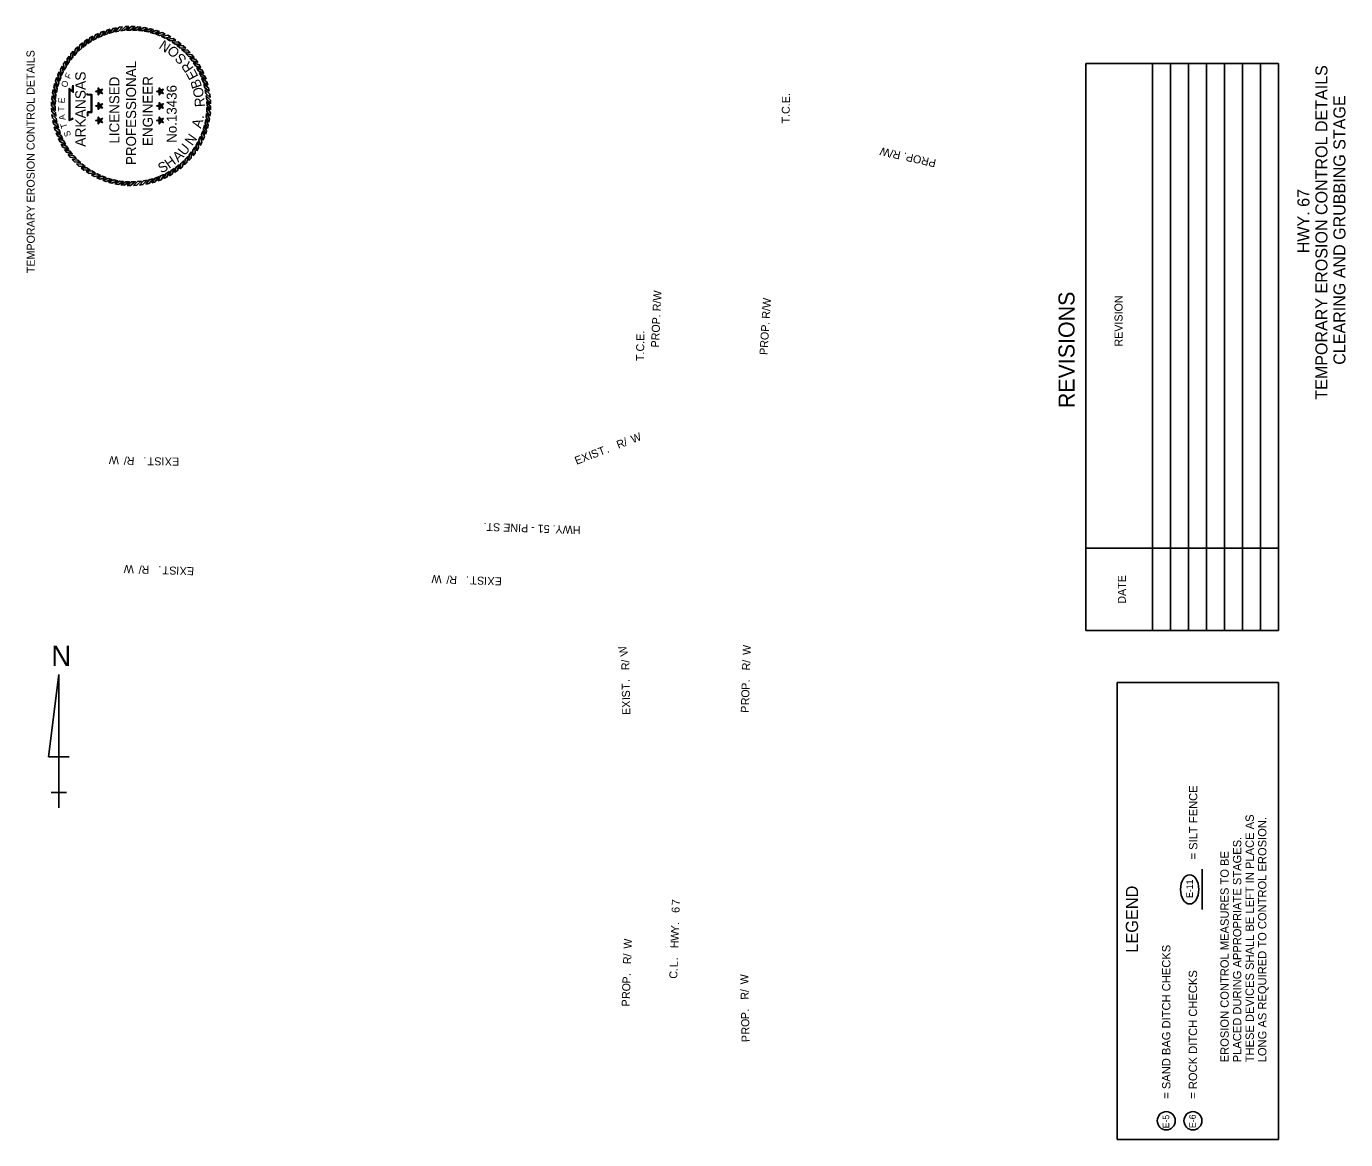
# Model space of a CAD drawing. Extents: x 992013 to 993002, y 1842718 to 1844294.
# Drawn here: x 992013 to 993002, y 1843459 to 1844294 of the extents above; entities that cross this region are included whole.
import ezdxf

# ---------------------------------------------------------------- set-up
doc = ezdxf.new("R2010")
doc.units = 0
for name, color, linetype in [('60', 7, 'Continuous'), ('63', 7, 'Continuous'), ('G-ANNO-SYMB', 7, 'Continuous'), ('G-ANNO-TEXT', 7, 'Continuous'), ('G-Border-Sheet', 7, 'Continuous'), ('Level 1', 7, 'Continuous'), ('Level 44', 7, 'Continuous'), ('R_Draft', 7, 'Continuous')]:
    doc.layers.add(name, color=color, linetype=linetype)

msp = doc.modelspace()

# ---------------------------------------------------------------- linework, layer by layer
at = {"layer": '63'}
for p, q in [((992036.87, 1843807.9), (992029.18, 1843746.36)), ((992036.87, 1843707.9), (992036.87, 1843807.9)), ((992036.87, 1843807.9), (992036.87, 1843730.97)), ((992029.18, 1843746.36), (992044.56, 1843746.36)), ((992036.87, 1843707.9), (992036.87, 1843730.97)), ((992036.87, 1843719.43), (992031.1, 1843719.43)), ((992031.1, 1843719.43), (992042.64, 1843719.43)), ((992036.87, 1843707.9), (992036.87, 1843719.43))]:
    msp.add_line(p, q, dxfattribs=at)
at = {"layer": 'G-ANNO-SYMB'}
for points in [[(992084.69, 1844293.56), (992082.14, 1844293.23), (992079.02, 1844289.88), (992081.75, 1844290.4)], [(992089.36, 1844293.87), (992086.8, 1844293.75), (992083.43, 1844290.66), (992086.18, 1844290.96)], [(992094.04, 1844293.82), (992091.48, 1844293.9), (992087.88, 1844291.08), (992090.65, 1844291.17)], [(992098.71, 1844293.41), (992096.16, 1844293.68), (992092.35, 1844291.16), (992095.12, 1844291.03)], [(992103.33, 1844292.63), (992100.81, 1844293.1), (992096.81, 1844290.88), (992099.56, 1844290.53)], [(992058.45, 1844284.2), (992056.34, 1844282.75), (992055.07, 1844278.35), (992057.26, 1844280.05)], [(992062.47, 1844286.6), (992060.25, 1844285.32), (992058.65, 1844281.04), (992060.96, 1844282.56)], [(992066.67, 1844288.68), (992064.35, 1844287.58), (992062.42, 1844283.44), (992064.85, 1844284.78)], [(992071.02, 1844290.43), (992068.62, 1844289.52), (992066.37, 1844285.54), (992068.89, 1844286.68)], [(992075.49, 1844291.83), (992073.02, 1844291.11), (992070.47, 1844287.32), (992073.08, 1844288.25)], [(992080.05, 1844292.87), (992077.54, 1844292.35), (992074.7, 1844288.77), (992077.37, 1844289.5)], [(992107.87, 1844291.48), (992105.4, 1844292.15), (992101.23, 1844290.26), (992103.95, 1844289.7)], [(992112.31, 1844289.99), (992109.9, 1844290.85), (992105.6, 1844289.29), (992108.26, 1844288.51)], [(992116.62, 1844288.15), (992114.28, 1844289.2), (992109.87, 1844287.98), (992112.47, 1844287)], [(992120.77, 1844285.98), (992118.52, 1844287.21), (992114.03, 1844286.33), (992116.54, 1844285.16)], [(992124.74, 1844283.49), (992122.59, 1844284.89), (992118.05, 1844284.37), (992120.46, 1844283)], [(992047.69, 1844275.2), (992045.97, 1844273.3), (992045.77, 1844268.73), (992047.5, 1844270.9)], [(992051.04, 1844278.48), (992049.17, 1844276.72), (992048.62, 1844272.18), (992050.51, 1844274.2)], [(992054.63, 1844281.48), (992052.64, 1844279.87), (992051.72, 1844275.39), (992053.77, 1844277.26)], [(992128.5, 1844280.69), (992126.47, 1844282.26), (992121.9, 1844282.1), (992124.19, 1844280.54)], [(992132.03, 1844277.61), (992130.13, 1844279.33), (992125.56, 1844279.53), (992127.72, 1844277.8)], [(992135.31, 1844274.27), (992133.54, 1844276.13), (992129, 1844276.69), (992131.03, 1844274.79)], [(992138.31, 1844270.67), (992136.7, 1844272.67), (992132.22, 1844273.58), (992134.08, 1844271.53)], [(992039.33, 1844263.95), (992038.1, 1844261.69), (992038.97, 1844257.2), (992040.15, 1844259.71)], [(992041.82, 1844267.91), (992040.42, 1844265.76), (992040.93, 1844261.22), (992042.31, 1844263.63)], [(992044.61, 1844271.67), (992043.05, 1844269.64), (992043.2, 1844265.07), (992044.76, 1844267.36)], [(992141.02, 1844266.85), (992139.57, 1844268.97), (992135.18, 1844270.23), (992136.88, 1844268.04)], [(992143.43, 1844262.83), (992142.15, 1844265.06), (992137.87, 1844266.66), (992139.39, 1844264.34)], [(992035.32, 1844255.49), (992034.46, 1844253.07), (992036.02, 1844248.77), (992036.79, 1844251.43)], [(992037.16, 1844259.79), (992036.11, 1844257.45), (992037.33, 1844253.05), (992038.31, 1844255.64)], [(992145.51, 1844258.64), (992144.41, 1844260.95), (992140.27, 1844262.89), (992141.6, 1844260.46)], [(992147.26, 1844254.29), (992146.34, 1844256.69), (992142.36, 1844258.94), (992143.5, 1844256.41)], [(992148.66, 1844249.82), (992147.93, 1844252.28), (992144.14, 1844254.84), (992145.08, 1844252.23)], [(992032.68, 1844246.5), (992032.21, 1844243.98), (992034.42, 1844239.98), (992034.77, 1844242.73)], [(992033.82, 1844251.05), (992033.15, 1844248.57), (992035.05, 1844244.41), (992035.61, 1844247.12)], [(992067.31, 1844245.15), (992066.47, 1844245.76), (992064.58, 1844245.15), (992066.47, 1844244.54)], [(992067.31, 1844245.15), (992067.63, 1844246.14), (992066.47, 1844247.74), (992066.47, 1844245.76)], [(992067.31, 1844245.15), (992066.47, 1844244.54), (992066.47, 1844242.56), (992067.63, 1844244.16)], [(992067.31, 1844245.15), (992068.35, 1844245.15), (992069.52, 1844246.75), (992067.63, 1844246.14)], [(992067.31, 1844245.15), (992067.63, 1844244.16), (992069.52, 1844243.55), (992068.35, 1844245.15)], [(992112.99, 1844245.15), (992112.15, 1844245.76), (992110.26, 1844245.15), (992112.15, 1844244.54)], [(992112.99, 1844245.15), (992113.31, 1844246.14), (992112.15, 1844247.74), (992112.15, 1844245.76)], [(992112.99, 1844245.15), (992112.15, 1844244.54), (992112.15, 1844242.56), (992113.31, 1844244.16)], [(992112.99, 1844245.15), (992114.03, 1844245.15), (992115.2, 1844246.75), (992113.31, 1844246.14)], [(992112.99, 1844245.15), (992113.31, 1844244.16), (992115.2, 1844243.55), (992114.03, 1844245.15)], [(992149.7, 1844245.25), (992149.17, 1844247.76), (992145.59, 1844250.61), (992146.33, 1844247.94)], [(992150.38, 1844240.62), (992150.05, 1844243.16), (992146.71, 1844246.28), (992147.23, 1844243.56)], [(992031.48, 1844237.22), (992031.41, 1844234.65), (992034.22, 1844231.05), (992034.14, 1844233.82)], [(992031.9, 1844241.88), (992031.62, 1844239.33), (992034.15, 1844235.52), (992034.28, 1844238.29)], [(992067.31, 1844234.24), (992066.47, 1844234.85), (992064.58, 1844234.24), (992066.47, 1844233.63)], [(992067.31, 1844234.24), (992067.63, 1844235.23), (992066.47, 1844236.83), (992066.47, 1844234.85)], [(992067.31, 1844234.24), (992066.47, 1844233.63), (992066.47, 1844231.65), (992067.63, 1844233.25)], [(992067.31, 1844234.24), (992068.35, 1844234.24), (992069.52, 1844235.84), (992067.63, 1844235.23)], [(992067.31, 1844234.24), (992067.63, 1844233.25), (992069.52, 1844232.64), (992068.35, 1844234.24)], [(992112.99, 1844234.24), (992112.15, 1844234.85), (992110.26, 1844234.24), (992112.15, 1844233.63)], [(992112.99, 1844234.24), (992113.31, 1844235.23), (992112.15, 1844236.83), (992112.15, 1844234.85)], [(992112.99, 1844234.24), (992112.15, 1844233.63), (992112.15, 1844231.65), (992113.31, 1844233.25)], [(992112.99, 1844234.24), (992114.03, 1844234.24), (992115.2, 1844235.84), (992113.31, 1844235.23)], [(992112.99, 1844234.24), (992113.31, 1844233.25), (992115.2, 1844232.64), (992114.03, 1844234.24)], [(992150.7, 1844235.94), (992150.57, 1844238.51), (992147.48, 1844241.88), (992147.79, 1844239.12)], [(992150.65, 1844231.26), (992150.72, 1844233.83), (992147.91, 1844237.43), (992148, 1844234.66)], [(992031.43, 1844232.53), (992031.56, 1844229.97), (992034.65, 1844226.6), (992034.34, 1844229.36)], [(992031.75, 1844227.86), (992032.08, 1844225.32), (992035.42, 1844222.2), (992034.9, 1844224.92)], [(992067.31, 1844223.33), (992066.47, 1844223.94), (992064.58, 1844223.33), (992066.47, 1844222.72)], [(992067.31, 1844223.33), (992067.63, 1844224.32), (992066.47, 1844225.92), (992066.47, 1844223.94)], [(992067.31, 1844223.33), (992068.35, 1844223.33), (992069.52, 1844224.93), (992067.63, 1844224.32)], [(992112.99, 1844223.33), (992112.15, 1844223.94), (992110.26, 1844223.33), (992112.15, 1844222.72)], [(992112.99, 1844223.33), (992113.31, 1844224.32), (992112.15, 1844225.92), (992112.15, 1844223.94)], [(992112.99, 1844223.33), (992114.03, 1844223.33), (992115.2, 1844224.93), (992113.31, 1844224.32)], [(992148.31, 1844217.43), (992148.98, 1844219.91), (992147.08, 1844224.07), (992146.52, 1844221.36)], [(992149.45, 1844221.98), (992149.92, 1844224.5), (992147.71, 1844228.5), (992147.36, 1844225.75)], [(992150.23, 1844226.59), (992150.51, 1844229.15), (992147.98, 1844232.96), (992147.85, 1844230.19)], [(992032.43, 1844223.23), (992032.96, 1844220.72), (992036.54, 1844217.87), (992035.81, 1844220.54)], [(992033.48, 1844218.66), (992034.2, 1844216.2), (992037.99, 1844213.64), (992037.05, 1844216.25)], [(992034.88, 1844214.19), (992035.79, 1844211.79), (992039.77, 1844209.54), (992038.63, 1844212.07)], [(992067.31, 1844223.33), (992066.47, 1844222.72), (992066.47, 1844220.74), (992067.63, 1844222.34)], [(992067.31, 1844223.33), (992067.63, 1844222.34), (992069.52, 1844221.73), (992068.35, 1844223.33)], [(992112.99, 1844223.33), (992112.15, 1844222.72), (992112.15, 1844220.74), (992113.31, 1844222.34)], [(992112.99, 1844223.33), (992113.31, 1844222.34), (992115.2, 1844221.73), (992114.03, 1844223.33)], [(992144.98, 1844208.69), (992146.02, 1844211.03), (992144.8, 1844215.43), (992143.82, 1844212.84)], [(992146.81, 1844212.99), (992147.68, 1844215.41), (992146.11, 1844219.71), (992145.34, 1844217.05)], [(992036.62, 1844209.84), (992037.72, 1844207.53), (992041.87, 1844205.59), (992040.53, 1844208.02)], [(992038.7, 1844205.65), (992039.98, 1844203.42), (992044.27, 1844201.82), (992042.74, 1844204.14)], [(992140.31, 1844200.57), (992141.72, 1844202.72), (992141.2, 1844207.26), (992139.83, 1844204.85)], [(992142.8, 1844204.53), (992144.03, 1844206.79), (992143.16, 1844211.27), (992141.98, 1844208.77)], [(992041.11, 1844201.63), (992042.56, 1844199.51), (992046.95, 1844198.25), (992045.25, 1844200.44)], [(992043.82, 1844197.81), (992045.43, 1844195.81), (992049.91, 1844194.9), (992048.05, 1844196.95)], [(992046.83, 1844194.21), (992048.59, 1844192.35), (992053.13, 1844191.79), (992051.11, 1844193.69)], [(992131.09, 1844190), (992132.96, 1844191.76), (992133.51, 1844196.3), (992131.62, 1844194.28)], [(992134.44, 1844193.28), (992136.16, 1844195.18), (992136.36, 1844199.75), (992134.63, 1844197.58)], [(992137.52, 1844196.81), (992139.09, 1844198.84), (992138.93, 1844203.41), (992137.37, 1844201.12)], [(992050.1, 1844190.87), (992052.01, 1844189.14), (992056.57, 1844188.95), (992054.41, 1844190.68)], [(992053.63, 1844187.79), (992055.66, 1844186.22), (992060.23, 1844186.38), (992057.94, 1844187.94)], [(992057.39, 1844184.99), (992059.54, 1844183.59), (992064.08, 1844184.11), (992061.68, 1844185.48)], [(992115.46, 1844179.8), (992117.78, 1844180.9), (992119.71, 1844185.04), (992117.28, 1844183.7)], [(992119.66, 1844181.88), (992121.88, 1844183.16), (992123.48, 1844187.44), (992121.17, 1844185.92)], [(992123.68, 1844184.28), (992125.8, 1844185.73), (992127.06, 1844190.13), (992124.87, 1844188.43)], [(992127.5, 1844187), (992129.5, 1844188.61), (992130.41, 1844193.09), (992128.36, 1844191.22)], [(992061.36, 1844182.5), (992063.61, 1844181.27), (992068.1, 1844182.14), (992065.59, 1844183.32)], [(992065.51, 1844180.33), (992067.85, 1844179.28), (992072.26, 1844180.5), (992069.67, 1844181.48)], [(992069.82, 1844178.49), (992072.24, 1844177.63), (992076.53, 1844179.19), (992073.87, 1844179.97)], [(992074.26, 1844177), (992076.74, 1844176.33), (992080.9, 1844178.22), (992078.18, 1844178.78)], [(992078.8, 1844175.85), (992081.32, 1844175.38), (992085.32, 1844177.6), (992082.57, 1844177.94)], [(992083.42, 1844175.07), (992085.97, 1844174.8), (992089.78, 1844177.32), (992087.02, 1844177.45)], [(992088.09, 1844174.65), (992090.65, 1844174.58), (992094.25, 1844177.4), (992091.48, 1844177.31)], [(992092.77, 1844174.6), (992095.33, 1844174.73), (992098.7, 1844177.82), (992095.95, 1844177.52)], [(992097.44, 1844174.92), (992099.99, 1844175.25), (992103.11, 1844178.6), (992100.38, 1844178.08)], [(992102.08, 1844175.61), (992104.59, 1844176.13), (992107.44, 1844179.71), (992104.76, 1844178.98)], [(992106.65, 1844176.65), (992109.11, 1844177.37), (992111.66, 1844181.16), (992109.06, 1844180.22)], [(992111.12, 1844178.05), (992113.51, 1844178.96), (992115.76, 1844182.94), (992113.24, 1844181.8)]]:
    msp.add_lwpolyline(points, close=True, dxfattribs=at)
for points in [[(992047.77, 1844224.68), (992044.75, 1844223.29), (992044.74, 1844247.36), (992047.27, 1844245.34), (992047.24, 1844246.98), (992047.23, 1844248.34), (992047.38, 1844249.71)], [(992047.61, 1844225.03), (992045.13, 1844223.89), (992045.12, 1844246.56), (992047.66, 1844244.55), (992047.63, 1844246.98), (992047.61, 1844248.33), (992047.75, 1844249.67)], [(992057.55, 1844243.32), (992057.97, 1844242.82), (992058.61, 1844242.64), (992059.91, 1844242.5), (992061.21, 1844242.5), (992061.21, 1844229.83), (992059.35, 1844229.83), (992058.57, 1844229.83), (992058.3, 1844228.96), (992058.3, 1844227.2), (992057.96, 1844226.97)], [(992057.85, 1844243.56), (992058.18, 1844243.15), (992058.68, 1844243.02), (992059.93, 1844242.88), (992061.59, 1844242.88), (992061.59, 1844229.45), (992059.35, 1844229.45), (992058.85, 1844229.45), (992058.68, 1844228.9), (992058.68, 1844226.99), (992058.16, 1844226.65)]]:
    msp.add_lwpolyline(points, dxfattribs=at)
at = {"layer": 'G-Border-Sheet'}
for p, q in [((992951.38, 1843801.93), (992830.33, 1843801.93)), ((992830.33, 1843459.27), (992830.33, 1843801.93)), ((992951.38, 1843459.27), (992951.38, 1843801.93)), ((992951.38, 1843459.27), (992830.33, 1843459.27))]:
    msp.add_line(p, q, dxfattribs=at)
at = {"layer": 'Level 1'}
for centre, major_axis, ratio in [((992884.7, 1843646.9), (0, 10.96), 0.622952), ((992867.16, 1843473.37), (0, -6.88), 0.97521), ((992887.16, 1843473.37), (0, -6.88), 0.97521)]:
    msp.add_ellipse(centre, major_axis=major_axis, ratio=ratio, dxfattribs=at)
at = {"layer": 'Level 44'}
msp.add_lwpolyline([(992894.03, 1843631.84), (992894.02, 1843661.96)], dxfattribs=at)
at = {"layer": 'R_Draft'}
for p, q in [((992806.88, 1843840.99), (992806.88, 1844265.99)), ((992806.88, 1844265.99), (992951.38, 1844265.99)), ((992856.88, 1843840.99), (992856.88, 1844265.99)), ((992870.38, 1843840.99), (992870.38, 1844265.99)), ((992883.88, 1843840.99), (992883.88, 1844265.99)), ((992897.38, 1843840.99), (992897.38, 1844265.99)), ((992897.38, 1843840.99), (992897.38, 1844265.99)), ((992910.88, 1843840.99), (992910.88, 1844265.99)), ((992924.38, 1843840.99), (992924.38, 1844265.99)), ((992937.88, 1843840.99), (992937.88, 1844265.99)), ((992951.38, 1843840.99), (992951.38, 1844265.99)), ((992806.88, 1843902.8), (992951.38, 1843902.8)), ((992806.88, 1843840.99), (992951.38, 1843840.99))]:
    msp.add_line(p, q, dxfattribs=at)

# ---------------------------------------------------------------- texts
at = {"layer": '60'}
for s, p in [('TEMPORARY EROSION CONTROL DETAILS', (992988.01, 1844014.05)), ('CLEARING AND GRUBBING STAGE ', (993001.51, 1844040.2)), ('HWY. 67 ', (992974.51, 1844123.82))]:
    msp.add_text(s, height=9, rotation=90, dxfattribs=at).set_placement(p)
at = {"layer": '63'}
msp.add_text('N', height=15.38, rotation=0, dxfattribs=at).set_placement((992031.24, 1843814.31))
at = {"layer": 'G-ANNO-SYMB'}
for s, height, rotation, p in [('N', 7.5, 146.10067, (992121.5, 1844279.98)), ('O', 7.5, 134.77573, (992128.25, 1844274.77)), ('S', 7.5, 133.48784, (992133.23, 1844269.62)), ('PROFESSIONAL', 7.5, 90, (992094.82, 1844189.95)), ('R', 7.5, 125.65967, (992138.33, 1844262.72)), ('F', 4.75, 65.36282, (992045.3, 1844254.08)), ('ARKANSAS', 7.747, 90, (992056.98, 1844203.62)), ('LICENSED', 7.5, 90, (992082.27, 1844206.03)), ('ENGINEER', 7.5, 90, (992107.36, 1844204.24)), ('E', 7.5, 117.83149, (992141.65, 1844256.38)), ('B', 7.5, 108.88501, (992144.36, 1844248.81)), ('O', 4.75, 71.2218, (992042.8, 1844247.68)), ('No.13436', 7.47, 90, (992125.24, 1844206.61)), ('O', 7.5, 101.42961, (992145.95, 1844241.29)), ('E', 4.75, 86.67203, (992041.17, 1844236.15)), ('R', 7.5, 93.22866, (992146.43, 1844233.62)), ('T', 4.75, 91.47887, (992041.03, 1844230.08)), ('A', 4.75, 98.67877, (992041.97, 1844223.95)), ('.', 7.5, 81.30002, (992145.48, 1844224.42)), ('T', 4.75, 106.90148, (992043.48, 1844218.18)), ('S', 4.75, 109.77256, (992046.19, 1844212.15)), ('A', 7.5, 73.09908, (992143.3, 1844217.05)), ('U', 7.5, 50.90262, (992131.28, 1844196.42)), ('N', 7.5, 54.93262, (992136.86, 1844203.97)), ('H', 7.5, 35.61905, (992119.54, 1844186.98)), ('A', 7.5, 43.44722, (992126.39, 1844191.74)), ('S', 7.5, 28.16364, (992113.66, 1844183.56))]:
    msp.add_text(s, height=height, rotation=rotation, dxfattribs=at).set_placement(p)
at = {"layer": 'G-ANNO-TEXT'}
msp.add_text('TEMPORARY EROSION CONTROL DETAILS', height=6, rotation=90.07909, dxfattribs=at).set_placement((992018.89, 1844108.85))
at = {"layer": 'Level 1'}
for s, height, p in [('= SILT FENCE', 6.25, (992890.48, 1843669.33)), ('THESE DEVICES SHALL BE LEFT IN PLACE AS ', 6.25, (992932.84, 1843517.24)), ('LONG AS REQUIRED TO CONTROL EROSION.', 6.25, (992942.25, 1843517.24)), ('PLACED DURING APPROPRIATE STAGES. ', 6.25, (992923.43, 1843517.24)), ('EROSION CONTROL MEASURES TO BE', 6.25, (992914.02, 1843517.24)), ('E-11 ', 4.876, (992887.1, 1843640.5)), ('= SAND BAG DITCH CHECKS', 6.25, (992870.28, 1843489.9)), ('= ROCK DITCH CHECKS', 6.25, (992890.28, 1843489.9)), ('E-5 ', 4.876, (992869.38, 1843467.73)), ('E-6 ', 4.876, (992889.29, 1843467.95))]:
    msp.add_text(s, height=height, rotation=90.00001, dxfattribs=at).set_placement(p)
at = {"layer": 'Level 44'}
msp.add_text('LEGEND', height=9.143, rotation=90.00001, dxfattribs=at).set_placement((992846.03, 1843599.41))
at = {"layer": 'R_Draft'}
for s, height, rotation, p in [('T.C.E.', 6, 89.40901, (992584.79, 1844221.09)), ('PROP. R/W', 6, 167.44815, (992695, 1844194.05)), ('PROP. R/W', 6, 87.28268, (992486.79, 1844053.02)), ('PROP. R/W', 6, 86.36556, (992568.15, 1844047.4)), ('REVISIONS', 12, 90, (992798.38, 1844007.65)), ('REVISION', 6, 90, (992834.38, 1844053.86)), ('T.C.E.', 6, 89.40901, (992475.66, 1844042.97)), ('W', 6, 20.9463, (992467.19, 1843981.28)), ('S', 6, 20.9463, (992437.32, 1843969.85)), ('T', 6, 20.9463, (992442.61, 1843971.88)), ('R', 6, 20.9463, (992456.42, 1843977.16)), ('/', 6, 20.9463, (992461.71, 1843979.19)), ('W', 6, 178.24464, (992082.11, 1843971.49)), ('/', 6, 178.24464, (992087.97, 1843971.31)), ('R', 6, 178.24464, (992093.64, 1843971.13)), ('.', 6, 178.24464, (992102.56, 1843970.86)), ('T', 6, 179.30223, (992108.31, 1843970.81)), ('S', 6, 179.30223, (992113.98, 1843970.74)), ('I', 6, 179.30223, (992115.96, 1843970.72)), ('X', 6, 179.30223, (992121.72, 1843970.65)), ('E', 6, 179.30223, (992127.11, 1843970.58)), ('E', 6, 20.9463, (992425.05, 1843965.15)), ('X', 6, 20.9463, (992430.08, 1843967.08)), ('I', 6, 20.9463, (992435.46, 1843969.14)), ('.', 6, 20.9463, (992448.08, 1843973.97)), ('HWY. 51 - PINE ST.', 6, 178.05575, (992428.12, 1843919.22)), ('W', 6, 178.15992, (992093.27, 1843889.83)), ('/', 6, 178.15992, (992099.12, 1843889.65)), ('R', 6, 178.15992, (992104.79, 1843889.46)), ('.', 6, 178.15992, (992113.71, 1843889.18)), ('T', 6, 178.15992, (992119.57, 1843888.99)), ('S', 6, 178.15992, (992125.24, 1843888.81)), ('I', 6, 178.15992, (992127.22, 1843888.74)), ('X', 6, 178.15992, (992132.98, 1843888.56)), ('E', 6, 178.15992, (992138.36, 1843888.38)), ('W', 6, 178.05575, (992324, 1843882.29)), ('/', 6, 178.05575, (992329.86, 1843882.1)), ('R', 6, 178.05575, (992335.52, 1843881.9)), ('.', 6, 178.05575, (992344.45, 1843881.6)), ('T', 6, 178.05575, (992350.3, 1843881.4)), ('S', 6, 178.05575, (992355.97, 1843881.21)), ('I', 6, 178.05575, (992357.95, 1843881.14)), ('X', 6, 178.05575, (992363.71, 1843880.95)), ('E', 6, 178.05575, (992369.1, 1843880.76)), ('DATE', 6, 90, (992836.88, 1843861.06)), ('W', 6, 104.91415, (992463.85, 1843822.71)), ('W', 6, 88.2004, (992555.51, 1843822.51)), ('/', 6, 91.02618, (992464.63, 1843816.94)), ('/', 6, 88.2004, (992555.32, 1843816.65)), ('R', 6, 91.02618, (992464.73, 1843811.28)), ('R', 6, 88.2004, (992555.14, 1843810.98)), ('T', 6, 91.02618, (992465, 1843796.49)), ('.', 6, 91.02618, (992464.89, 1843802.35)), ('P', 6, 88.2004, (992554.69, 1843796.39)), ('.', 6, 88.2004, (992554.86, 1843802.06)), ('S', 6, 91.02618, (992465.1, 1843790.82)), ('I', 6, 91.02618, (992465.14, 1843788.84)), ('R', 6, 88.2004, (992554.32, 1843784.87)), ('O', 6, 88.2004, (992554.5, 1843790.54)), ('X', 6, 91.02618, (992465.24, 1843783.08)), ('E', 6, 91.02618, (992465.34, 1843777.69)), ('P', 6, 88.2004, (992554.15, 1843779.2)), ('6', 6, 88.03611, (992502.24, 1843629.19)), ('7', 6, 88.03611, (992502.43, 1843634.86)), ('.', 6, 88.03611, (992501.93, 1843620.27)), ('W', 6, 88.03611, (992501.52, 1843608.09)), ('Y', 6, 88.03611, (992501.74, 1843614.51)), ('W', 6, 88.03611, (992466.3, 1843602.26)), ('H', 6, 88.03611, (992501.33, 1843602.71)), ('/', 6, 88.03611, (992466.09, 1843596.41)), ('R', 6, 88.03611, (992465.9, 1843590.74)), ('L', 6, 88.03611, (992500.84, 1843588.4)), ('.', 6, 88.03611, (992501.03, 1843593.78)), ('P', 6, 88.03611, (992465.4, 1843576.15)), ('.', 6, 88.03611, (992465.59, 1843581.82)), ('C', 6, 88.03611, (992500.55, 1843579.81)), ('.', 6, 88.03611, (992500.74, 1843585.47)), ('W', 6, 91.21594, (992553.9, 1843575.77)), ('O', 6, 88.03611, (992465.2, 1843570.3)), ('/', 6, 91.21594, (992554.03, 1843569.92)), ('P', 6, 88.03611, (992464.81, 1843558.97)), ('R', 6, 88.03611, (992465.01, 1843564.63)), ('R', 6, 91.21594, (992554.15, 1843564.25)), ('P', 6, 91.21594, (992554.46, 1843549.65)), ('.', 6, 91.21594, (992554.34, 1843555.32)), ('O', 6, 91.21594, (992554.58, 1843543.8)), ('R', 6, 91.21594, (992554.7, 1843538.13)), ('P', 6, 91.21594, (992554.82, 1843532.46))]:
    msp.add_text(s, height=height, rotation=rotation, dxfattribs=at).set_placement(p)

doc.saveas('drawing.dxf')
